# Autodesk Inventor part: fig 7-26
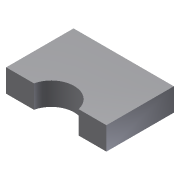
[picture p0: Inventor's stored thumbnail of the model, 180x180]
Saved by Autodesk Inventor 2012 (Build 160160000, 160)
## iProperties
Created: 2005-04
Part Number: fig 7-26
Document SubType Name: Modeling
Designer: CADCIM
Density: 1 g/cm^3
Material: Default
Author: CADCIM
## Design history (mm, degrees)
sketch "Sketch1"
  geometry: L1 (9.851, -16.047)-(9.851, -1.297); L2 (9.851, -1.297)-(-12.082, -1.297); L3 (-12.082, -1.297)-(-12.082, -16.047); L4 (-12.082, -16.047)-(9.851, -16.047)
  constraints: 8 end point, 2 parallel, 1 perpendicular, 1 vertical
extrude "Extrusion1" new body sketch "Sketch1" distance "d0" = 5; taper "d1" = 0 deg
sketch "Sketch2"
  geometry: C1 r 5 at (-1.115, -17.135); 1 further point
  constraints: 1 centre point
  dimensions: "d7" = 10.96654 horizontal distance of point (-12.082, -16.047) C1.centre; "d8" = 10 diameter of C1
extrude "Extrusion2" cut sketch "Sketch2" stored distance "d2" = 5; taper "d3" = 0 deg
body "Solid1"
